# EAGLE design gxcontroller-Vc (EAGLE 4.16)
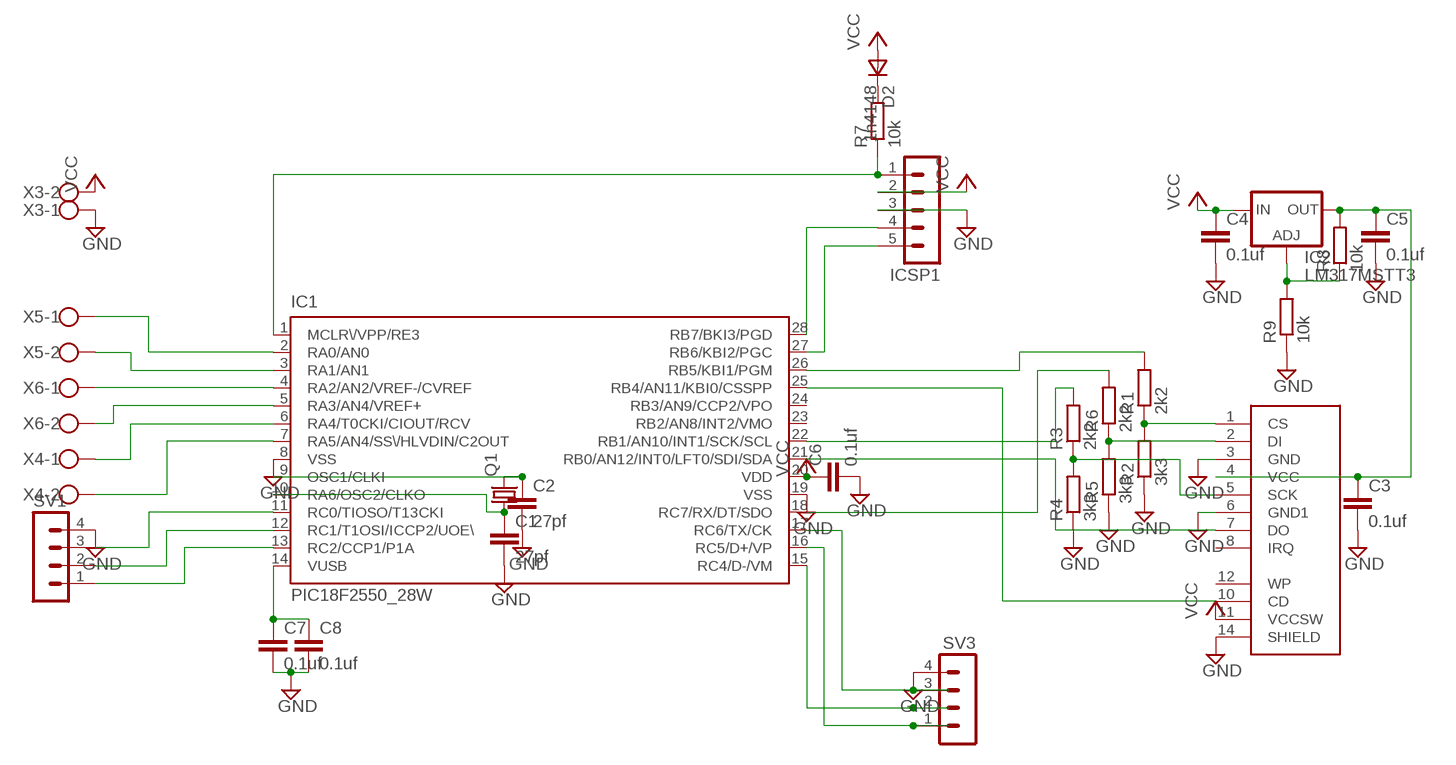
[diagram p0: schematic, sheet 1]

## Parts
C1  27pf  C-EUC0805K  [C0805K]
C2  27pf  C-EUC0805K  [C0805K]
C3  0.1uf  C-EUC0805K  [C0805K]
C4  0.1uf  C-EUC0805K  [C0805K]
C5  0.1uf  C-EUC0805K  [C0805K]
C6  0.1uf  C-EUC0805K  [C0805K]
C7  0.1uf  C-EUC0805K  [C0805K]
C8  0.1uf  C-EUC0805K  [C0805K]
D2  1n4148  DSOT23  [SOT-23]
IC1  PIC18F2550_28W  [SO28W]
IC2  LM317MSTT3  [SOT223]
ICSP1  MA05-1  [MA05-1]
Q1  CRYSTALHC49UP  [HC49UP]
R1  2k2  R-EU_0204/7  [0204/7]
R2  3k3  R-EU_0204/7  [0204/7]
R3  2k2  R-EU_0207/12  [0207/12]
R4  3k3  R-EU_0204/7  [0204/7]
R5  3k3  R-EU_0204/7  [0204/7]
R6  2k2  R-EU_0204/7  [0204/7]
R7  10k  R-EU_R1206  [R1206]
R8  10k  R-EU_R0805  [R0805]
R9  10k  R-EU_R0805  [R0805]
SD1  ALPS-SCDA1A0901  [ALPS-A9]
SV1  MA04-1  [MA04-1]
SV3  MA04-1  [MA04-1]
X3  W237-102  [W237-102]
X4  W237-102  [W237-102]
X5  W237-102  [W237-102]
X6  W237-102  [W237-102]

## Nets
GND: C1.2 C2.2 C3.2 C4.2 C5.2 C6.2 C7.2 C8.2 IC1.8(VSS) IC1.19(VSS) ICSP1.3 R2.1 R4.1 R5.1 R9.1 SD1.3(GND) SD1.6(GND1) SD1.14(SHIELD) SV1.4 SV3.4 X3.1
N$1: C2.1 IC1.9(OSC1/CLKI) Q1.2
N$2: C1.1 IC1.10(RA6/OSC2/CLKO) Q1.1
N$3: C7.1 C8.1 IC1.14(VUSB)
N$4: R1.1 R2.2 SD1.1(CS)
N$5: R5.2 R6.1 SD1.2(DI)
N$6: R3.1 R4.2 SD1.5(SCK)
N$7: IC1.25(RB4/AN11/KBI0/CSSPP) SD1.10(CD)
N$8: C3.1 C5.1 IC2.4(OUT) R8.2 SD1.4(VCC)
N$9: IC1.21(RB0/AN12/INT0/LFT0/SDI/SDA) SD1.7(DO)
N$10: IC1.18(RC7/RX/DT/SDO) R6.2
N$11: IC1.22(RB1/AN10/INT1/SCK/SCL) R3.2
N$12: IC1.1(MCLR\/VPP/RE3) ICSP1.1 R7.1
N$13: IC1.27(RB6/KBI2/PGC) ICSP1.5
N$14: IC1.2(RA0/AN0) X5.1
N$15: IC1.28(RB7/BKI3/PGD) ICSP1.4
N$16: IC2.1(ADJ) R8.1 R9.2
N$17: D2.1(C) R7.2
N$18: IC1.17(RC6/TX/CK) SV3.3
N$19: IC1.3(RA1/AN1) X5.2
N$20: IC1.4(RA2/AN2/VREF-/CVREF) X6.1
N$21: IC1.5(RA3/AN4/VREF+) X6.2
N$22: IC1.6(RA4/T0CKI/CIOUT/RCV) X4.1
N$23: IC1.26(RB5/KBI1/PGM) R1.2
N$24: IC1.7(RA5/AN4/SS\/HLVDIN/C2OUT) X4.2
N$25: IC1.11(RC0/TIOSO/T13CKI) SV1.3
N$26: IC1.12(RC1/T1OSI/ICCP2/UOE\) SV1.2
N$27: IC1.13(RC2/CCP1/P1A) SV1.1
RC4: IC1.15(RC4/D-/VM) SV3.2
RC5: IC1.16(RC5/D+/VP) SV3.1
VCC: C4.1 C6.1 D2.3(A) IC1.20(VDD) IC2.3(IN) ICSP1.2 SD1.11(VCCSW) X3.2
Unconnected: IC1.23(RB2/AN8/INT2/VMO) IC1.24(RB3/AN9/CCP2/VPO) SD1.8(IRQ) SD1.12(WP)

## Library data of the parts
C1-C8 = rcl:C-EU: CAPACITOR, European symbol
D2 = zetex:D: DIODE
IC1 = microchip:PIC18F2*_28: USB Microcontrollers with nanoWatt Technology High-Performance, Enhanced Flash, 28/40/44-Pin, Source: http://ww1.microchip.com/downloads/en/devicedoc/39632c.pdf
IC2 = v-reg:LM317?*: 500 mA Adjustable Output Positive Voltage Regulator Source: http://www.onsemi.co.jp .. LM317M-D.PDF
ICSP1 = con-lstb:MA05-1: PIN HEADER
Q1 = crystal:CRYSTAL: CRYSTAL
R1-R9 = rcl:R-EU_: RESISTOR, European symbol
SD1 = AlpsSDCard:ALPS-SCDA1A0901
SV1 SV3 = con-lstb:MA04-1: PIN HEADER
X3-X6 = con-wago-500:W237-102: WAGO SCREW CLAMP

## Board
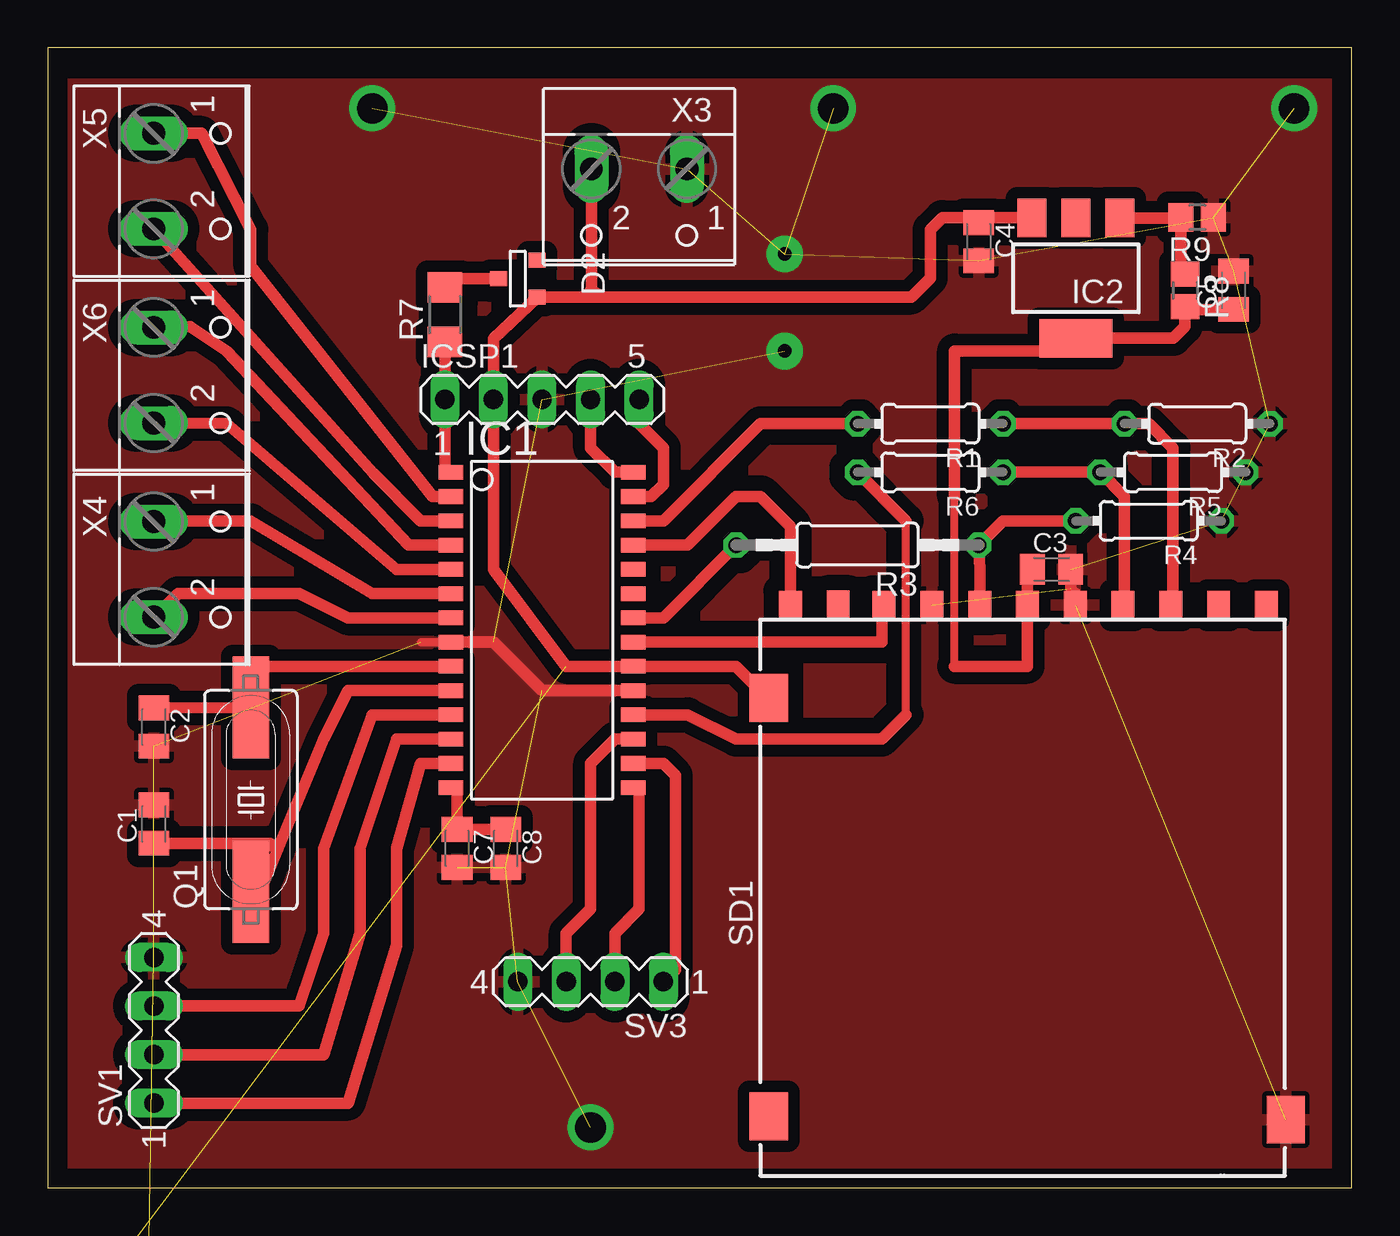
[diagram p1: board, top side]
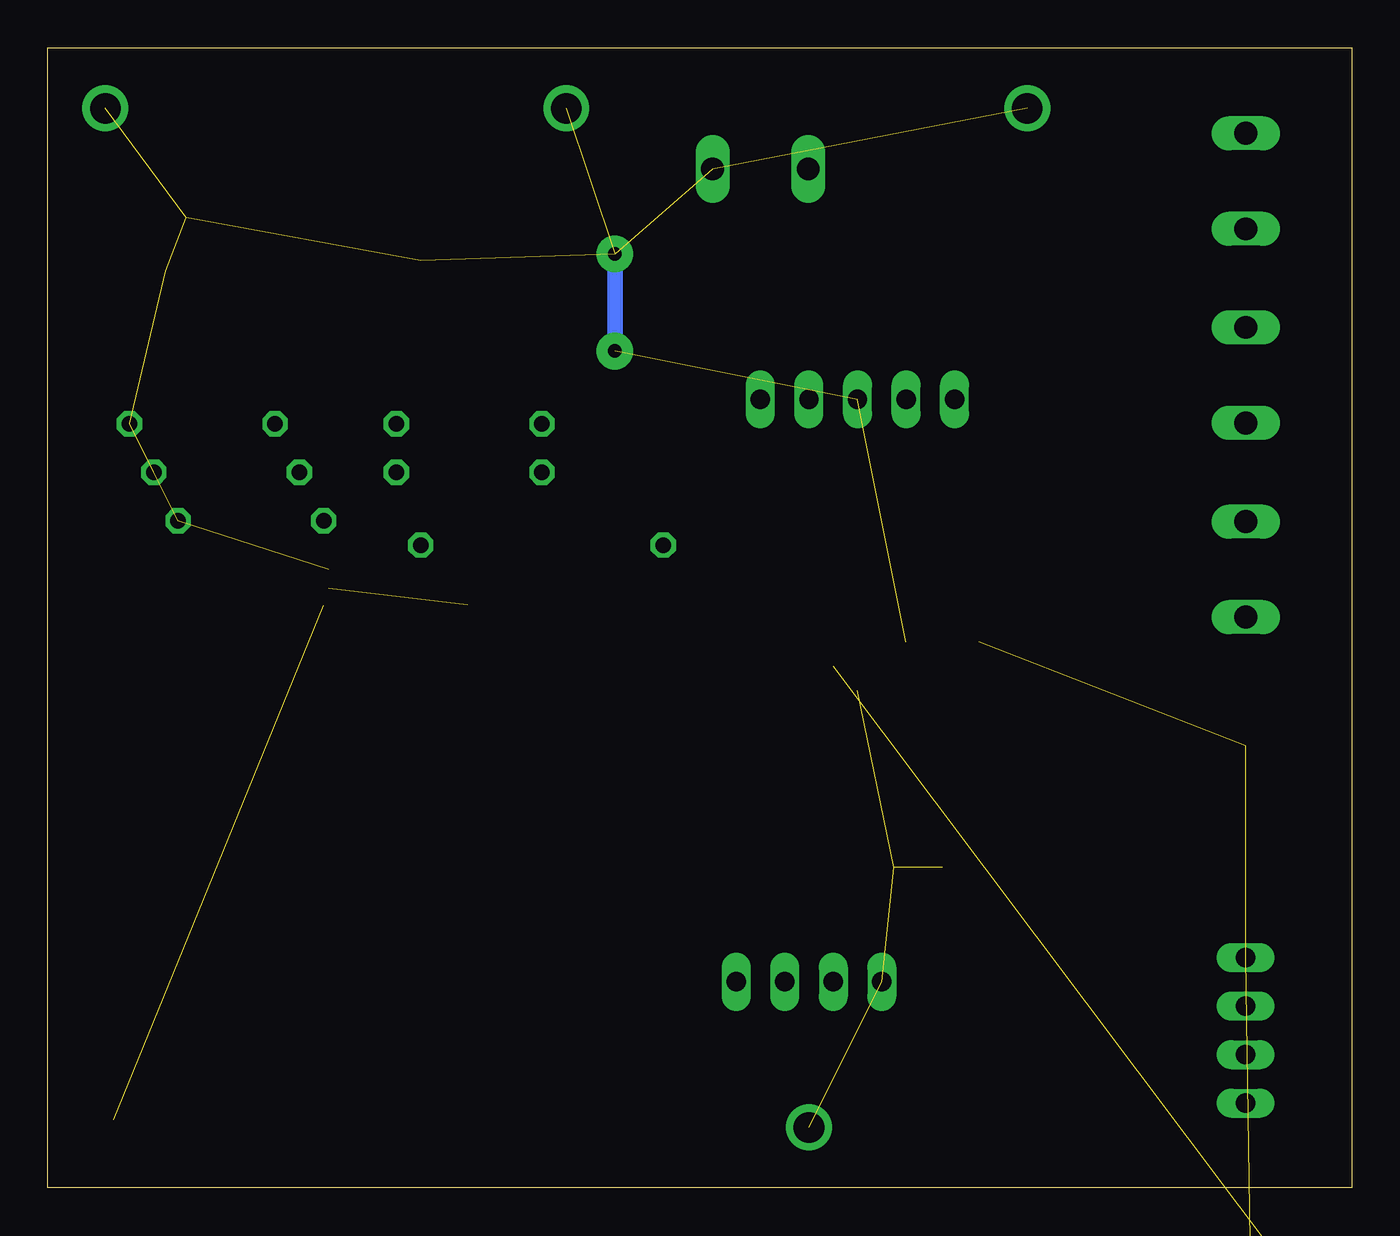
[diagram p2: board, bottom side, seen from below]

Size 68.25 x 59.68 mm. Coordinates in mm from the lower left corner, seen from the top.
Outline: 0,0 68.25,0 68.25,59.68 0,59.68 0,0
Copper layers (1*16): Top 0.035mm / dielectric 1.5mm / Bottom 0.035mm
Design rules "default": minimum track width 10mil, minimum drill 24mil, track to track 8mil, track to pad 8mil, pad to pad 8mil, via to via 8mil, smd to smd 8mil, copper to edge 40mil, drill to drill 8mil, minimum pad ring 10mil, minimum via ring 8mil, stop-mask expansion 4mil, vias tented up to drill 0mil, thermal gap 10mil

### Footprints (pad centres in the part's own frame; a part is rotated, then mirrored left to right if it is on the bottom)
C0805K = smd 1.3 x 1.6: 1 -1,0; 2 1,0
SOT-23 = smd 0.787 x 0.889: 1 0.025,-1.016; 2 -0.94,1.016; 3 0.991,1.016
SO28W = smd 0.762 x 1.27: 1 -7.62,-4.78; 2 -6.35,-4.78; 3 -5.08,-4.78; 4 -3.81,-4.78; 5 -2.54,-4.78; 6 -1.27,-4.78; 7 0,-4.78; 8 1.27,-4.78; 9 2.54,-4.78; 10 3.81,-4.78; 11 5.08,-4.78; 12 6.35,-4.78; 13 7.62,-4.78; 14 8.89,-4.78; 15 8.89,4.78; 16 7.62,4.78; 17 6.35,4.78; 18 5.08,4.78; 19 3.81,4.78; 20 2.54,4.78; 21 1.27,4.78; 22 0,4.78; 23 -1.27,4.78; 24 -2.54,4.78; 25 -3.81,4.78; 26 -5.08,4.78; 27 -6.35,4.78; 28 -7.62,4.78
SOT223 = smd 1.5 x 2: 1 -2.3,-3.15; 2 0,-3.15; 3 2.3,-3.15 | smd 3.8 x 2: 4 0,3.15
MA05-1 = drill 1.016 long: 1 -5.08,0; 2 -2.54,0; 3 0,0; 4 2.54,0; 5 5.08,0
HC49UP = smd 5.334 x 1.93: 1 -4.826,0; 2 4.826,0
0204/7 = drill 0.813 octagon: 1 -3.81,0; 2 3.81,0
0207/12 = drill 0.813 octagon: 1 -6.35,0; 2 6.35,0
R1206 = smd 1.6 x 1.803: 1 -1.422,0; 2 1.422,0
R0805 = smd 1.3 x 1.5: 1 -0.85,0; 2 0.85,0
ALPS-A9 = smd 1.2 x 1.5: 1 21.48,29.87; 2 18.98,29.87; 3 16.48,29.87; 4 13.98,29.87; 5 11.48,29.87; 6 8.98,29.87; 7 6.46,29.87; 8 4.072,29.89; 9 23.98,29.87; 10 1.562,29.868; 13-NC 26.48,29.87 | smd 2 x 2.5: 11 0.435,25.02; 12 0.435,3.12; 14 27.502,2.945
MA04-1 = drill 1.016 long: 1 -3.81,0; 2 -1.27,0; 3 1.27,0; 4 3.81,0
W237-102 = drill 1.194 long: 1 -2.5,-1.27; 2 2.5,-1.27

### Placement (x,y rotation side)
C1  5.55,19.04 90 top
C2  5.55,24.12 270 top
C3  52.54,32.38 0 top
C4  48.73,49.53 270 top
C5  62.06,46.98 90 top
C6  not placed on the board
C7  21.42,17.77 270 top
C8  23.96,17.77 270 top
D2  24.6,47.62 270 top
IC1  25.87,29.84 270 top
IC2  53.81,47.62 180 top
ICSP1  25.87,41.27 0 top
Q1  10.63,20.31 90 top
R1  46.19,40 180 top
R2  60.16,40 180 top
R3  42.38,33.65 180 top
R4  57.62,34.92 180 top
R5  58.89,37.46 180 top
R6  46.19,37.46 180 top
R7  20.79,45.72 90 top
R8  59.52,46.98 270 top
R9  60.16,50.8 180 top
SD1  37.3,0.63 0 top
SV1  5.55,8.25 90 top
SV3  28.41,10.79 180 top
X3  30.95,52.07 180 top
X4  6.82,32.38 270 top
X5  6.82,52.7 270 top
X6  6.82,42.54 270 top

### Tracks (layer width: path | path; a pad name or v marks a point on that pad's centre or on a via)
GND  (via drill 0.7 pad 1.93, 1.6)  (23 unrouted)
  Top 0.406: 53.81,31.11 53.54,31.38 | 53.81,30.47 SD1.3 | 19.52,28.57 22.06,28.57
  Top 0.61: IC1.8 22.06,28.57 23.33,28.57 25.87,26.03 IC1.19 30.95,26.03 | 53.54,31.38 C3.2 | 53.81,30.47 53.81,31.11
  Bottom 0.813: v38.57,43.81 v38.57,48.89
  other vias: 28.41,3.17 16.98,56.51 41.11,56.51 65.24,56.51
  pour Top (isolate 0.61): 0.47,0.63 67.78,0.63 67.78,57.78 0.47,57.78
N$1
  Top 0.61: C2.1 Q1.2 10.63,27.3 IC1.9
N$2
  Top 0.61: IC1.10 15.71,26.03 14.44,23.49 12.04,17.72 | Q1.1 10.63,15.87 11.27,15.87 12.04,17.72 | 12.04,17.72 11.96,17.72 11.63,18.04 C1.1
N$3
  Top 0.406: 20.79,20.95 IC1.14 21.42,20.95 | C7.1 21.42,18.41
  Top 0.61: C8.1 C7.1 21.42,20.95
N$4
  Top 0.406: 58.89,30.47 58.87,30.5 SD1.1
  Top 0.61: R1.1 R2.2 57.62,40 58.89,38.73 58.89,30.47
N$5
  Top 0.406: 56.35,30.47 56.32,30.5 SD1.2
  Top 0.61: R6.1 R5.2 56.35,36.19 56.35,30.47
N$6
  Top 0.61: SD1.5 48.78,32.33 R3.1 50,34.92 R4.2
N$7
  Top 0.61: IC1.25 33.49,33.65 36.03,36.19 37.3,36.19 38.86,34.63 SD1.10
N$8
  Top 0.406: 59.89,45.98 59.52,46.35 R8.2 | 52.54,44.47 IC2.4 | 51.27,31.11 51.27,30.47 SD1.4 | 51.27,32.38 C3.1 | 47.46,27.3 47.46,36.19
  Top 0.61: 59.89,45.98 C5.1 | IC2.4 58.91,44.47 59.52,45.08 59.52,46.35 | 52.54,44.47 52.54,43.81 47.46,43.81 47.46,36.19 | 47.46,27.3 51.27,27.3 51.27,30.47 51.27,32.38
N$9
  Top 0.406: 43.65,30.47 43.67,30.5 SD1.7
  Top 0.61: IC1.21 43.65,28.57 43.65,30.47
N$10
  Top 0.406: 44.92,24.76 44.92,34.92
  Top 0.61: IC1.18 33.49,24.76 36.03,23.49 43.65,23.49 44.92,24.76 | 44.92,34.92 R6.2
N$11
  Top 0.61: IC1.22 32.22,29.84 R3.2
N$12
  Top 0.406: IC1.1 20.79,37.46
  Top 0.61: 20.79,37.46 ICSP1.1 R7.1
N$13
  Top 0.61: ICSP1.5 30.95,40 32.22,38.73 32.22,36.83 31.58,36.19 IC1.27
N$14
  Top 0.61: X5.1 8.05,55.2 10.63,50.16 10.63,48.26 20.15,36.19 IC1.2
N$15
  Top 0.61: IC1.28 29.68,37.46 28.41,38.73 ICSP1.4
N$16
  Top 0.61: IC2.1 59.5,50.77 59.52,50.8 R9.2 59.31,47.84 59.52,47.62 R8.1
N$17
  Top 0.406: 20.81,47.6 20.79,47.62 R7.2
  Top 0.61: 20.81,47.6 D2.1
N$18
  Top 0.406: IC1.17 30.95,23.49
  Top 0.61: IC1.17 29.68,23.49 28.41,22.22 28.41,17.14 28.41,14.6 27.14,13.33 SV3.3
N$19
  Top 0.61: X5.2 17.02,37.42 19.52,34.92 IC1.3
N$20
  Top 0.61: IC1.4 18.88,33.65 9.36,43.81 7.46,45.08 X6.1
N$21
  Top 0.61: IC1.5 18.25,32.38 9.36,40 X6.2
N$22
  Top 0.406: X4.1 5.55,34.92
  Top 0.61: IC1.6 16.98,31.11 10.63,34.92 5.55,34.92
N$23
  Top 0.61: IC1.26 32.22,34.92 37.3,40 R1.2
N$24
  Top 0.61: IC1.7 15.71,29.84 13.17,31.11 6.82,31.11 5.55,29.84 X4.2
N$25
  Top 0.61: IC1.11 16.98,24.76 14.44,17.77 14.44,13.33 13.17,9.52 SV1.3
N$26
  Top 0.61: SV1.2 14.44,6.98 16.34,13.33 16.34,17.77 18.25,23.49 IC1.12
N$27
  Top 0.61: SV1.1 15.71,4.44 18.25,12.7 18.25,17.77 19.52,22.22 IC1.13
N$28
  pour Top (isolate 0.813): 0.47,57.78 67.78,57.78 67.78,0.63 0.47,0.63
RC4
  Top 0.406: 30.95,20.95 IC1.15
  Top 0.61: 30.95,20.95 30.95,14.6 29.68,13.33 SV3.2
RC5
  Top 0.61: IC1.16 32.22,22.22 32.85,21.58 32.85,11.43 SV3.1
VCC  (1 unrouted)
  Top 0.406: 37.73,25.59 SD1.11 | 51.27,50.16 51.27,50.8 51.3,50.77 IC2.3 49.34,50.77 48.73,50.16 C4.1
  Top 0.61: 37.94,25.39 37.73,25.59 36.03,27.3 IC1.20 27.14,27.3 23.33,32.38 ICSP1.2 23.33,44.45 25.62,46.6 D2.3 29.04,46.63 | 51.27,50.8 46.82,50.8 46.19,50.16 46.19,47.62 45.2,46.63 29.04,46.63 | 29.04,46.63 28.41,46.98 28.45,46.95 X3.2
